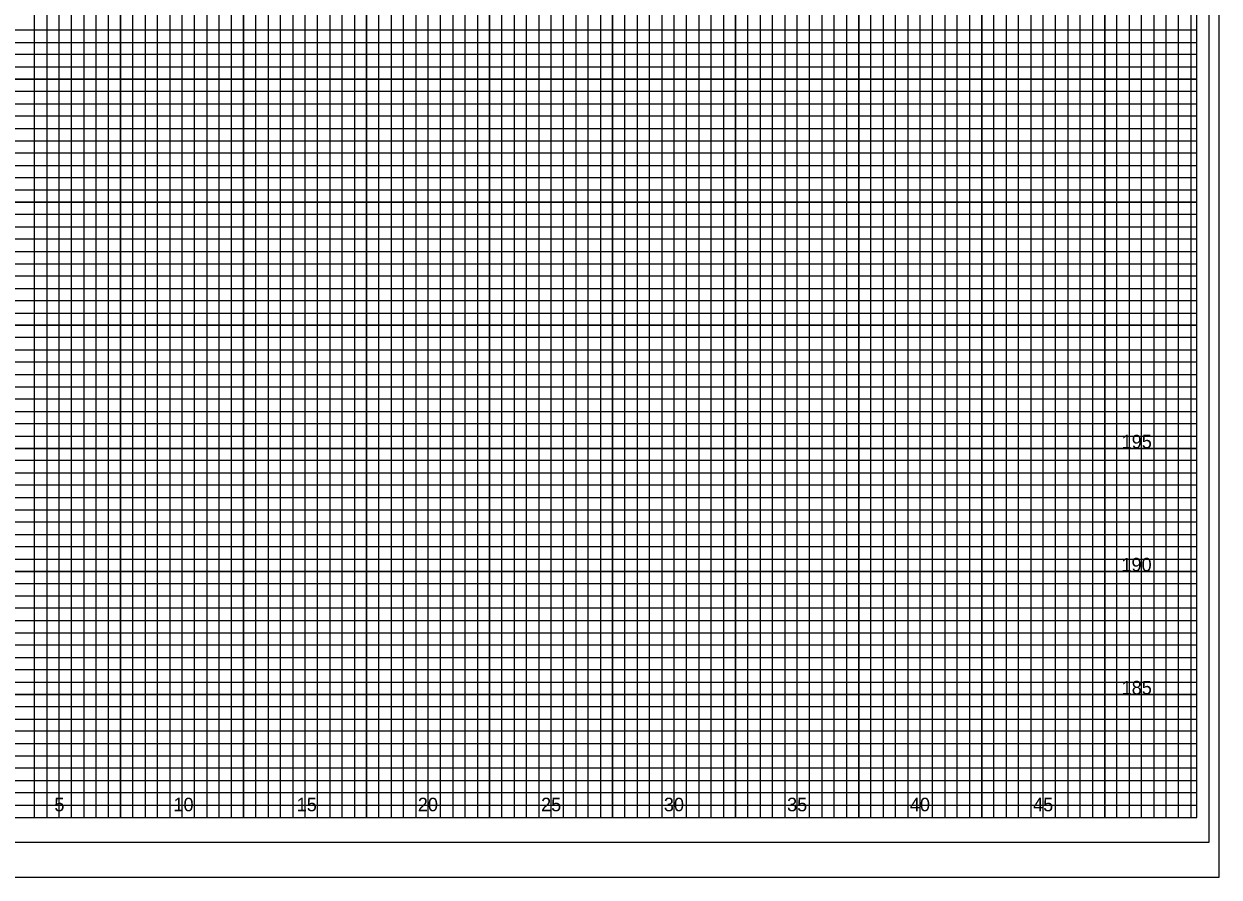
# Model space of a CAD drawing. Extents: x -4 to 103, y -2 to 138.
# Drawn here: x 54.82 to 103.4, y 68.4 to 103.08 of the extents above; entities that cross this region are included whole.
import ezdxf

# ---------------------------------------------------------------- set-up
doc = ezdxf.new("R2010")
doc.units = 0
for name, color, linetype in [('Old_Level_10', 7, 'Continuous'), ('Old_Level_16', 7, 'Continuous'), ('Old_Level_3', 7, 'Continuous'), ('Old_Level_5', 7, 'Continuous'), ('Old_Level_8', 7, 'Continuous'), ('Prop Dimension', 7, 'Continuous'), ('Prop XS SE Text', 7, 'Continuous'), ('Prop XS Subgrade Earthwork', 7, 'Continuous'), ('Prop XSC Text', 7, 'Continuous')]:
    doc.layers.add(name, color=color, linetype=linetype)

msp = doc.modelspace()

# ---------------------------------------------------------------- linework, layer by layer
at = {"layer": 'Old_Level_10'}
for p, q in [((56.25, 70.825), (56.25, 135.825)), ((58.75, 70.825), (58.75, 135.825)), ((61.25, 70.825), (61.25, 135.825)), ((63.75, 70.825), (63.75, 135.825)), ((66.25, 70.825), (66.25, 135.825)), ((68.75, 70.825), (68.75, 135.825)), ((71.25, 70.825), (71.25, 135.825)), ((73.75, 70.825), (73.75, 135.825)), ((91.25, 70.825), (91.25, 134.25)), ((93.75, 70.825), (93.75, 134.25)), ((96.25, 70.825), (96.25, 134.25)), ((98.75, 70.825), (98.75, 134.25)), ((101.25, 70.825), (101.25, 134.25)), ((76.25, 70.825), (76.25, 132.825)), ((78.75, 70.825), (78.75, 132.825)), ((81.25, 70.825), (81.25, 132.825)), ((83.75, 70.825), (83.75, 132.825)), ((86.25, 70.825), (86.25, 132.825)), ((88.75, 70.825), (88.75, 132.825)), ((0, 100.825), (102.5, 100.825)), ((0, 98.325), (102.5, 98.325)), ((0, 95.825), (102.5, 95.825)), ((0, 93.325), (102.5, 93.325)), ((0, 90.825), (102.5, 90.825)), ((0, 88.325), (102.5, 88.325)), ((0, 85.825), (102.5, 85.825)), ((0, 83.325), (102.5, 83.325)), ((0, 80.825), (102.5, 80.825)), ((0, 78.325), (102.5, 78.325)), ((0, 75.825), (102.5, 75.825)), ((0, 73.325), (102.5, 73.325))]:
    msp.add_line(p, q, dxfattribs=at)
at = {"layer": 'Old_Level_3'}
msp.add_line((-3.5, 68.4), (103.4, 68.4), dxfattribs=at)
at = {"layer": 'Old_Level_5'}
msp.add_lwpolyline([(103.4, 138.225), (-3.5, 138.225), (-3.5, 68.4), (103.4, 68.4)], close=True, dxfattribs=at)
at = {"layer": 'Old_Level_8'}
for points in [[(56.25, 70.825), (56.25, 135.825)], [(58.75, 135.825), (58.75, 70.825), (61.25, 70.825), (61.25, 135.825)], [(63.75, 135.825), (63.75, 70.825), (66.25, 70.825), (66.25, 135.825)], [(68.75, 135.825), (68.75, 70.825), (71.25, 70.825), (71.25, 135.825)], [(73.75, 135.825), (73.75, 70.825), (76.25, 70.825), (76.25, 132.825)], [(88.75, 132.825), (88.75, 70.825), (91.25, 70.825), (91.25, 134.25)], [(93.75, 134.25), (93.75, 70.825), (96.25, 70.825), (96.25, 134.25)], [(98.75, 134.25), (98.75, 70.825), (101.25, 70.825), (101.25, 134.25)], [(78.75, 132.825), (78.75, 70.825), (81.25, 70.825), (81.25, 132.825)], [(83.75, 132.825), (83.75, 70.825), (86.25, 70.825), (86.25, 132.825)], [(0, 98.325), (102.5, 98.325), (102.5, 100.825), (0, 100.825)], [(0, 93.325), (102.5, 93.325), (102.5, 95.825), (0, 95.825)], [(0, 88.325), (102.5, 88.325), (102.5, 90.825), (0, 90.825)], [(0, 83.325), (102.5, 83.325), (102.5, 85.825), (0, 85.825)], [(0, 78.325), (102.5, 78.325), (102.5, 80.825), (0, 80.825)], [(0, 73.325), (102.5, 73.325), (102.5, 75.825), (0, 75.825)]]:
    msp.add_lwpolyline(points, dxfattribs=at)
at = {"layer": 'Prop Dimension'}
for points in [[(54.75, 70.825), (55.25, 70.825), (55.25, 135.825)], [(55.75, 135.825), (55.75, 70.825), (56.75, 70.825), (56.75, 135.825)], [(57.25, 135.825), (57.25, 70.825), (57.75, 70.825), (57.75, 135.825)], [(58.25, 135.825), (58.25, 70.825), (59.25, 70.825), (59.25, 135.825)], [(59.75, 135.825), (59.75, 70.825), (60.25, 70.825), (60.25, 135.825)], [(60.75, 135.825), (60.75, 70.825), (61.75, 70.825), (61.75, 135.825)], [(62.25, 135.825), (62.25, 70.825), (62.75, 70.825), (62.75, 135.825)], [(63.25, 135.825), (63.25, 70.825), (64.25, 70.825), (64.25, 135.825)], [(64.75, 135.825), (64.75, 70.825), (65.25, 70.825), (65.25, 135.825)], [(65.75, 135.825), (65.75, 70.825), (66.75, 70.825), (66.75, 135.825)], [(67.25, 135.825), (67.25, 70.825), (67.75, 70.825), (67.75, 135.825)], [(68.25, 135.825), (68.25, 70.825), (69.25, 70.825), (69.25, 135.825)], [(69.75, 135.825), (69.75, 70.825), (70.25, 70.825), (70.25, 135.825)], [(70.75, 135.825), (70.75, 70.825), (71.75, 70.825), (71.75, 135.825)], [(72.25, 135.825), (72.25, 70.825), (72.75, 70.825), (72.75, 135.825)], [(73.25, 135.825), (73.25, 70.825), (74.25, 70.825), (74.25, 132.825)], [(89.75, 132.825), (89.75, 70.825), (90.25, 70.825), (90.25, 134.25)], [(90.75, 134.25), (90.75, 70.825), (91.75, 70.825), (91.75, 134.25)], [(92.25, 134.25), (92.25, 70.825), (92.75, 70.825), (92.75, 134.25)], [(93.25, 134.25), (93.25, 70.825), (94.25, 70.825), (94.25, 134.25)], [(94.75, 134.25), (94.75, 70.825), (95.25, 70.825), (95.25, 134.25)], [(95.75, 134.25), (95.75, 70.825), (96.75, 70.825), (96.75, 134.25)], [(97.25, 134.25), (97.25, 70.825), (97.75, 70.825), (97.75, 134.25)], [(98.25, 134.25), (98.25, 70.825), (99.25, 70.825), (99.25, 134.25)], [(99.75, 134.25), (99.75, 70.825), (100.25, 70.825), (100.25, 134.25)], [(100.25, 134.25), (100.75, 134.25), (100.75, 70.825), (101.75, 70.825), (101.75, 134.25), (102.25, 134.25), (102.25, 70.825)], [(74.75, 132.825), (74.75, 70.825), (75.25, 70.825), (75.25, 132.825)], [(75.75, 132.825), (75.75, 70.825), (76.75, 70.825), (76.75, 132.825)], [(77.25, 132.825), (77.25, 70.825), (77.75, 70.825), (77.75, 132.825)], [(78.25, 132.825), (78.25, 70.825), (79.25, 70.825), (79.25, 132.825)], [(79.75, 132.825), (79.75, 70.825), (80.25, 70.825), (80.25, 132.825)], [(80.75, 132.825), (80.75, 70.825), (81.75, 70.825), (81.75, 132.825)], [(82.25, 132.825), (82.25, 70.825), (82.75, 70.825), (82.75, 132.825)], [(83.25, 132.825), (83.25, 70.825), (84.25, 70.825), (84.25, 132.825)], [(84.75, 132.825), (84.75, 70.825), (85.25, 70.825), (85.25, 132.825)], [(85.75, 132.825), (85.75, 70.825), (86.75, 70.825), (86.75, 132.825)], [(87.25, 132.825), (87.25, 70.825), (87.75, 70.825), (87.75, 132.825)], [(88.25, 132.825), (88.25, 70.825), (89.25, 70.825), (89.25, 132.825)], [(0, 102.325), (102.5, 102.325), (102.5, 102.825), (0, 102.825)], [(0, 101.325), (102.5, 101.325), (102.5, 101.825), (0, 101.825)], [(0, 99.825), (102.5, 99.825), (102.5, 100.325), (0, 100.325)], [(0, 98.825), (102.5, 98.825), (102.5, 99.325), (0, 99.325)], [(0, 97.325), (102.5, 97.325), (102.5, 97.825), (0, 97.825)], [(0, 96.325), (102.5, 96.325), (102.5, 96.825), (0, 96.825)], [(0, 94.825), (102.5, 94.825), (102.5, 95.325), (0, 95.325)], [(0, 93.825), (102.5, 93.825), (102.5, 94.325), (0, 94.325)], [(0, 92.325), (102.5, 92.325), (102.5, 92.825), (0, 92.825)], [(0, 91.325), (102.5, 91.325), (102.5, 91.825), (0, 91.825)], [(0, 89.825), (102.5, 89.825), (102.5, 90.325), (0, 90.325)], [(0, 88.825), (102.5, 88.825), (102.5, 89.325), (0, 89.325)], [(0, 87.325), (102.5, 87.325), (102.5, 87.825), (0, 87.825)], [(0, 86.325), (102.5, 86.325), (102.5, 86.825), (0, 86.825)], [(0, 84.825), (102.5, 84.825), (102.5, 85.325), (0, 85.325)], [(0, 83.825), (102.5, 83.825), (102.5, 84.325), (0, 84.325)], [(0, 82.325), (102.5, 82.325), (102.5, 82.825), (0, 82.825)], [(0, 81.325), (102.5, 81.325), (102.5, 81.825), (0, 81.825)], [(0, 79.825), (102.5, 79.825), (102.5, 80.325), (0, 80.325)], [(0, 78.825), (102.5, 78.825), (102.5, 79.325), (0, 79.325)], [(0, 77.325), (102.5, 77.325), (102.5, 77.825), (0, 77.825)], [(0, 76.325), (102.5, 76.325), (102.5, 76.825), (0, 76.825)], [(0, 74.825), (102.5, 74.825), (102.5, 75.325), (0, 75.325)], [(0, 73.825), (102.5, 73.825), (102.5, 74.325), (0, 74.325)], [(0, 72.325), (102.5, 72.325), (102.5, 72.825), (0, 72.825)], [(0, 71.325), (102.5, 71.325), (102.5, 71.825), (0, 71.825)]]:
    msp.add_lwpolyline(points, dxfattribs=at)
at = {"layer": 'Prop XS SE Text'}
msp.add_lwpolyline([(103, 136.825), (-2.8, 136.825), (-2.8, 69.825), (103, 69.825)], close=True, dxfattribs=at)
at = {"layer": 'Prop XSC Text'}
msp.add_lwpolyline([(102.5, 135.825), (0, 135.825), (0, 70.825), (102.5, 70.825)], close=True, dxfattribs=at)

# ---------------------------------------------------------------- texts
at = {"layer": 'Old_Level_16'}
for s, p in [('5', (56.057, 71.075)), ('10', (60.897, 71.075)), ('15', (65.906, 71.075)), ('20', (70.831, 71.075)), ('25', (75.84, 71.075)), ('30', (80.831, 71.075)), ('35', (85.84, 71.075)), ('40', (90.831, 71.075)), ('45', (95.84, 71.075))]:
    msp.add_text(s, height=0.55, dxfattribs=at).set_placement(p)
at = {"layer": 'Prop XS Subgrade Earthwork'}
for s, p in [('195', (99.438, 85.825)), ('190', (99.43, 80.825)), ('185', (99.438, 75.825))]:
    msp.add_text(s, height=0.55, dxfattribs=at).set_placement(p)

doc.saveas('drawing.dxf')
